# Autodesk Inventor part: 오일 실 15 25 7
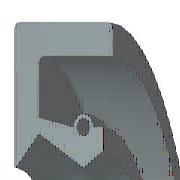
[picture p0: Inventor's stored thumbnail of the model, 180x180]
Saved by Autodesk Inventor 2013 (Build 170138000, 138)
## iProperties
Created: 2012-02
Part Number: 오일 실 15 25 7
Material: 고무
Description: 오일-실
Document SubType Name: Modeling
Standard: KS B 2804
Designer: mduedu
Standards Organization: KS
Language: ko-KR
Size Designation: D - 15 25 7
Categories: <MemberInstance><Categories><Category DisplayName="샤프트 부품" InternalName="7f7aeb1f-a693-4053-b835-cee3144e0d98" Mnemonic="SHFT"><Category DisplayName="실링" Intern
Density: 0.93 g/cm^3
Mass: 1.46464 g
Surface Area: 21.6685 cm^2
Volume: 1.57488 cm^3
IsCustomPart: 1
Author: mduedu
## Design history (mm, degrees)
revolve "본체" stored, may be unused: angle "d17" = 90 deg
revolve "스프링1" stored, may be unused: angle "d18" = 90 deg
body "Solid1"
sketch "스케치1"
  geometry: L1 (0, 12.5)-(7, 12.5); L2 (7, 10.75)-(1.75, 10.75); L3 (1.75, 9.25)-(4.9, 7.5); L4 (4.9, 7.5)-(0, 7.5); L5 (0, 0)-(9.586, 0) reference; L6 (4.9, 7.5)-(6.3, 8.375); L7 (0, 18)-(0, -3) reference; L8 (-1.941, 0)-(11.507, 0) reference; L9 (4.2, 9.6)-(1.75, 10.09); L10 (1.75, 10.09)-(1.75, 10.75); L11 (0, 12.5)-(0, 7.588); L12 (4.9, 7.5)-(0, 7.5); L13 (1.75, 9.25)-(0.152, 7.528); L14 (7, 12.5)-(7, 10.75); L15 (5.6, 9.6)-(6.3, 9.6); L16 (6.3, 9.6)-(6.3, 8.375); C1 r 0.455 at (4.9, 9.6); A1 r 0.7 centre (4.9, 9.6) between (5.6, 9.6) and (4.2, 9.6); A2 r 0.088 centre (0.088, 7.588) between (0, 7.588) and (0.152, 7.528); 1 further point
  constraints: 28 end point, 5 horizontal alignment, 5 point on line, 4 point on circle, 4 vertical alignment, 3 centre point, 3 tangent, 2 collinear, 2 horizontal, 2 perpendicular, 1 coincident, 1 parallel
  dimensions: "d0" = 25 diameter of L1 L5 (= SD2); "d1" = 1.75 distance of L1.end L2.start (= SD); "d2" = 0.91 diameter of C1 (= SPDI); "d3" = 1.4 diameter of A1 (= SPDA); "d4" = 15 diameter of L3.end L5 (= NND); "d5" = 18.5 diameter of L3.start L5 (= TKDM); "d7" = 20.18 diameter of L9.end L5 (= TKDM + 0.24 x SWDT); "d8" = 1.75 distance between parallel lines of L11 L10 (= SD); "d9" = 4.9 distance from line of L11 C1.centre (= SPDST); "d10" = 19.2 diameter of C1.centre L5 (= HLDM); "d11" = 0.0875 radius of A2 (= 0.25 x LAB); "d12" = 6.3 distance between parallel lines of L11 L16 (= SDI); "d13" = 16.75 diameter of L6.end L5 (= ABDM); "d14" = 7 distance from line of L11 L1.end (= SWDT)
fillet "모깎기1" dims "d6" = 0.3 (= RR)
other parameters: "SD2" = 25 [user parameter; used in 1 equation term], "SWDT" = 7 [user parameter; used in 2 equation terms], "RR" = 0.3 [user parameter; used in 1 equation term], "SD" = 1.75 [user parameter; used in 2 equation terms], "NND" = 15 [user parameter; used in 1 equation term], "SPDA" = 1.4 [user parameter; used in 1 equation term], "SPDI" = 0.91 [user parameter; used in 1 equation term], "TKDM" = 18.5 [user parameter; used in 2 equation terms], "HLDM" = 19.2 [user parameter; used in 1 equation term], "ABDM" = 16.75 [user parameter; used in 1 equation term], "SDI" = 6.3 [user parameter; used in 1 equation term], "SPDST" = 4.9 [user parameter; used in 1 equation term], "LAB" = 0.35 [user parameter; used in 1 equation term], "d15" = 0, "d16" = 0, "d19" = 0
